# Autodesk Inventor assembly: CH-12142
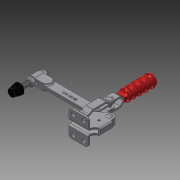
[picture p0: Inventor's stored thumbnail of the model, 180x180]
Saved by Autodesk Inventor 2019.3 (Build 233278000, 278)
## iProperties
Company: Î¢ÈíÖÐ¹ú
Created: 2012-09
Part Number: CH-12142
Material: Ogólny
Description: STEP AP203
Document SubType Name: Assembly
Designer: CADENGINEERING4
Stock Number: DOCISK PIONOWY
Sending System: SolidWorks 2010
Preprocessor: SwSTEP 2.0
Title: CH-12142.STEP
Author: Î¢ÈíÓÃ»§
Revision Number: ÈÎºÎ
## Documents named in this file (11)
- D:\Vault_2016\Projekty\Clamptek\STRONA\Vertical toggle clamp\CH-12142\CH-12142_ZAMKNIETY.iam
- D:\Vault_2016\Projekty\Clamptek\STRONA\Vertical toggle clamp\CH-12142\CH-12130-06.ipt
- D:\Vault_2016\Projekty\Clamptek\STRONA\Vertical toggle clamp\CH-12142\CH-12130-07.ipt
- D:\Vault_2016\Projekty\Clamptek\STRONA\Vertical toggle clamp\CH-12142\CH-FC-56212 Nut.ipt
- D:\Vault_2016\Projekty\Clamptek\STRONA\Vertical toggle clamp\CH-12142\CH-FC-56212 SPINDLE SUPPLIED.ipt
- D:\Vault_2016\Projekty\Clamptek\STRONA\Vertical toggle clamp\CH-12142\CH-12130-08.ipt
- D:\Vault_2016\Projekty\Clamptek\STRONA\Vertical toggle clamp\CH-12142\CH-12130-04 CONNECTING-PLATE.ipt
- D:\Vault_2016\Projekty\Clamptek\STRONA\Vertical toggle clamp\CH-12142\CH-12142-02 LONG SOLID BAR_Ä¬ÈÏ_°´¼Ó¹¤_.ipt
- D:\Vault_2016\Projekty\Clamptek\STRONA\Vertical toggle clamp\CH-12142\CH-12130-03 STRAIGHT HANDLE.ipt
- D:\Vault_2016\Projekty\Clamptek\STRONA\Vertical toggle clamp\CH-12142\CH-12130-05.ipt
- D:\Vault_2016\Projekty\Clamptek\STRONA\Vertical toggle clamp\CH-12142\CH-12130-01 FLANGED BASE.ipt
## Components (13 placed, 13 different names)
1. CH-12130-06_1
2. CH-12130-07_2
3. CH-FC-56212 Nut_3
4. CH-FC-56212 SPINDLE SUPPLIED_4
5. CH-12130-08_5
6. CH-12130-04 CONNECTING-PLATE_6
7. CH-12142-02 LONG SOLID BAR_Ä¬ÈÏ<°´¼Ó¹¤>_7
8. CH-12130-03 STRAIGHT HANDLE_8
9. CH-12130-06_9
10. CH-FC-56212 Nut_10
11. CH-12130-05_11
12. CH-12130-08_12
13. CH-12130-01 FLANGED BASE_13
